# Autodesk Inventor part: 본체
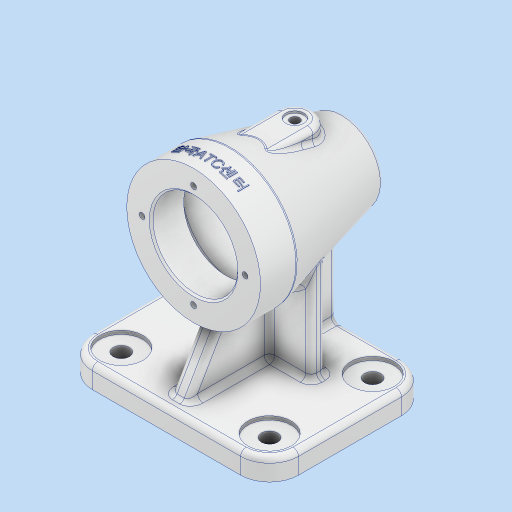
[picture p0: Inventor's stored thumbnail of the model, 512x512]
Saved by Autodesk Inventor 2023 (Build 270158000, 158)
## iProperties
Created: 2024-12
Part Number: 본체
Material: 알루미늄 6061
Document SubType Name: Modeling
Designer: asung
Density: 2.7 g/cm^3
Appearance: 알루미늄 - 평지
Mass: 739.493 g
Surface Area: 674.499 cm^2
Volume: 273.886 cm^3
Author: asung
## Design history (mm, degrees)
sketch "스케치1"
  geometry: L1 (-5744.5, -45.233)-(-5744.5, 45.233); L2 (5744.5, 45.233)-(5744.5, -45.233); L3 (41, -44.5)-(-41, -44.5); L4 (-57, -28.5)-(-57, 28.5); L5 (-41, 44.5)-(41, 44.5); L6 (57, 28.5)-(57, -28.5); L7 (57, -44.5)-(-57, 44.5); L8 (-57, -44.5)-(57, 44.5); A1 r 16 centre (41, -28.5) between (41, -44.5) and (57, -28.5); A2 r 16 centre (-41, -28.5) between (-57, -28.5) and (-41, -44.5); A3 r 16 centre (-41, 28.5) between (-41, 44.5) and (-57, 28.5); A4 r 16 centre (41, 28.5) between (57, 28.5) and (41, 44.5); 1 further point
  constraints: 16 end point, 8 point on circle, 8 point on line, 8 tangent, 4 centre point, 3 equal radius, 3 parallel, 2 midpoint, 1 horizontal, 1 perpendicular
  dimensions: "d1" = 114 distance of L7.end L8.end; "d2" = 89 distance of L8.start L7.end; "d3" = 16 radius of A1
extrude "돌출1" new body sketch "스케치1" distance "d4" = 12; taper "d5" = 0 deg
sketch "스케치2"
  geometry: A1 r 16 centre (41, -28.5) between (41, -44.5) and (57, -28.5) reference; A2 r 16 centre (41, 28.5) between (57, 28.5) and (41, 44.5) reference; A3 r 16 centre (-41, 28.5) between (-41, 44.5) and (-57, 28.5) reference; A4 r 16 centre (-41, -28.5) between (-57, -28.5) and (-41, -44.5) reference; 1 further point
hole "구멍1" sketch "스케치2" at (-41, 28.5), (-41, -28.5), (41, -28.5), (41, 28.5) diameter "d6" = 9; stored, may be unused: countersink angle "d10" = 90 deg, drill point angle "d12" = 0 deg; dims "d7" = 6, "d8" = 24, "d9" = 2, "d11" = 12
node "작업 평면1"
sketch "스케치4"
  geometry: L1 (73, 12)-(73, 0) reference; L2 (73, 0)-(-16, 0) reference; L3 (-16, 0)-(-16, 12) reference; L4 (-16, 12)-(73, 12) reference; L5 (73, 0)-(57, 0) reference; L6 (58, 82)-(58, 0); L7 (58, 82)-(-26, 82); L8 (-26, 82)-(-26, 103); L9 (58, 82)-(58, 119); L10 (58, 119)-(38, 119); L11 (38, 119)-(-26, 103); 1 further point
  constraints: 12 end point, 3 vertical, 2 horizontal
  dimensions: "d23" = 82 distance of L6.start L6.end; "d24" = 15 distance of L1.end L6.end; "d25" = 0 vertical distance of L1.end L6.end; "d26" = 84 distance of L6.start L7.end; "d29" = 37 distance of L6.start L9.end; "d30" = 20 distance of L9.end L10.end; "d118" = 42 diameter of L8.end L7
revolve "회전1" sketch "스케치4" stored, may be unused: angle "d32" = 90 deg
node "작업 평면2"
sketch "스케치5"
  geometry: L1 (-16.733, 29.5)-(16.733, 29.5) reference; L2 (16.733, 29.5)-(16.733, 9.5) reference; L3 (-16.733, 9.5)-(-16.733, 29.5) reference; L4 (-21, -54.5)-(21, -54.5) reference; L5 (-37, 9.5)-(37, 9.5) reference; L6 (-37, 9.5)-(37, 9.5) reference; L7 (-37, 29.5)-(37, 29.5) reference; L8 (-37, 29.5)-(37, 29.5) reference; L9 (0, 29.5)-(0, -26.5); L10 (10, -26.5)-(10, 4.324); L11 (-10, -26.5)-(-10, 7.832); L12 (-10, 7.832)-(10, 7.832); L13 (10, 7.832)-(10, 4.324); A1 r 10 centre (0, -26.5) between (10, -26.5) and (-10, -26.5); 3 further points
  constraints: 10 end point, 2 perpendicular, 2 point on circle, 2 tangent, 2 vertical, 1 centre point, 1 coincident, 1 midpoint, 1 parallel, 1 point on line, 1 other
  dimensions: "d35" = 56 distance of L9.start L9.end; "d36" = 20 diameter of A1
extrude "돌출2" join sketch "스케치5" stored distance "d37" = 12; taper "d38" = 0 deg
sketch "스케치6"
  geometry: L1 (58, 119)-(58, 45) reference; L2 (58, 45)-(38, 45) reference; L3 (38, 45)-(-26, 61) reference; L4 (-26, 61)-(-26, 103) reference; L5 (-26, 103)-(-8, 107.5) reference; L6 (-8, 107.5)-(-8, 115) reference; L7 (-8, 115)-(22, 115) reference; L8 (22, 115)-(38, 119) reference; L9 (38, 119)-(58, 119) reference; L10 (-16, 0)-(-16, 12) reference; L11 (-16, 12)-(73, 12) reference; L12 (73, 12)-(73, 0) reference; L13 (73, 0)-(-16, 0) reference; L14 (-16, 0)-(-16, 12) reference; L15 (-16, 12)-(-16, 65.487); L16 (35.119, 65.487)-(66, 12); L17 (58, 119)-(58, 45) reference; L18 (-26, 61)-(-26, 103) reference; L19 (-26, 103)-(-8, 107.5) reference; L20 (-8, 107.5)-(-8, 115) reference; L21 (-8, 115)-(22, 115) reference; L22 (38, 119)-(58, 119) reference; L23 (-16, 0)-(-16, 12) reference; L24 (-16, 12)-(73, 12) reference; L25 (73, 12)-(73, 0) reference; L26 (73, 0)-(-16, 0) reference; L27 (-16, 65.487)-(35.119, 65.487); L28 (22, 115)-(38, 119) reference; 2 further points; 2 other entities
  constraints: 6 end point, 1 horizontal, 1 point on line, 1 vertical, 2 other
  dimensions: "d39" = 7 distance from line of L12 L16.end; "d40" = 60 deg angle of L11 L16; "d41" = 65.48678 distance between parallel lines of L13 L27
extrude "돌출3" join sketch "스케치6" stored distance "d42" = 10; taper "d43" = 0 deg
node "작업 평면3"
sketch "스케치7"
  geometry: L1 (51, 115)-(51, 111.079) reference; L2 (46, 51.659)-(46, 12) reference; L3 (46, 12)-(98, 12) reference; L4 (98, 12)-(98, 0) reference; L5 (98, 0)-(-16, 0) reference; L6 (-16, 0)-(-16, 12) reference; L7 (-16, 12)-(36, 12) reference; L8 (36, 12)-(36, 51.659) reference; L9 (31, 111.079)-(31, 115) reference; L10 (31, 115)-(51, 115) reference; L11 (69, 69.289)-(69, 12); L12 (13, 69.289)-(13, 12); A1 r 30.75 centre (41, 82) between (46, 51.659) and (51, 111.079) reference; A2 r 30.75 centre (41, 82) between (31, 111.079) and (36, 51.659) reference; 1 further point
  constraints: 4 end point, 2 point on circle, 2 point on line, 2 vertical
  dimensions: "d45" = 56 distance of L12.end L11.end; "d46" = 28 horizontal distance of point (41, 0) L11.end
  node "절단 모서리 투영5"
feature "리브1" dims "d47" = 1, "d48" = 8, "d49" = 0, "d50" = 0, "d51" = 1, "d52" = 1
feature "리브2" dims "d53" = 1, "d54" = 8, "d55" = 0, "d56" = 0, "d57" = 1, "d58" = 1
sketch "스케치8"
  geometry: C1 r 37 at (0, 0) reference; 2 further points
  constraints: 1 coincident
hole "구멍2" sketch "스케치8" at (0, 0) diameter "d59" = 47; stored, may be unused: countersink angle "d63" = 90 deg, drill point angle "d65" = 0 deg; dims "d60" = 6, "d61" = 24, "d62" = 2, "d64" = 18
chamfer "모따기1" distance "d66" = 1; stored, may be unused: second distance "d67" = 2, angle "d68" = 45 deg
sketch "스케치9"
  geometry: L1 (61, -54.5)-(58.5, -44.5) reference; L2 (58.5, -44.5)-(0, -44.5) reference; L3 (0, -44.5)-(0, 44.5) reference; L4 (0, 44.5)-(12, 44.5) reference; L5 (12, 44.5)-(12, 37.5) reference; L6 (12, 37.5)-(45, 18.447) reference; L7 (45, 18.447)-(45, 29.5) reference; L8 (45, 29.5)-(57.5, 29.5) reference; L9 (57.5, 29.5)-(58.5, 28.5) reference; L10 (58.5, 28.5)-(58.5, 11.5) reference; L11 (58.5, 11.5)-(105.5, 11.5) reference; L12 (105.5, 11.5)-(105.5, 28.5) reference; L13 (105.5, 28.5)-(106.5, 29.5) reference; L14 (106.5, 29.5)-(119, 29.5) reference; L15 (119, 29.5)-(119, 9.5) reference; L16 (119, 9.5)-(115, -6.5) reference; L17 (115, -6.5)-(115, -36.5) reference; L18 (115, -36.5)-(107.5, -36.5) reference; L19 (107.5, -36.5)-(103, -54.5) reference; L20 (103, -54.5)-(61, -54.5) reference; L21 (112.793, 5.287)-(103.664, -31.228); L22 (82, -33.5)-(100.754, -33.5); L23 (105.5, 11.5)-(58.5, 11.5) reference; L24 (82, 11.5)-(82, -33.5); L25 (82, 11.5)-(107.942, 11.5); A1 r 5 centre (107.942, 6.5) between (112.793, 5.287) and (107.942, 11.5); A2 r 3 centre (100.754, -30.5) between (100.754, -33.5) and (103.664, -31.228); 3 further points
  constraints: 9 end point, 5 tangent, 4 point on circle, 3 parallel, 2 centre point, 1 midpoint
  dimensions: "d69" = 5 distance between parallel lines of L16 L21; "d70" = 45 distance between parallel lines of L11 L22; "d71" = 5 radius of A1; "d72" = 3 radius of A2
revolve "회전2" sketch "스케치9" stored, may be unused: angle "d73" = 90 deg
sketch "스케치10"
  geometry: C1 r 18.754 at (0, 0) reference; 2 further points
  constraints: 1 coincident
hole "구멍3" sketch "스케치10" at (0, 0) diameter "d74" = 31; stored, may be unused: countersink angle "d78" = 90 deg, drill point angle "d80" = 0 deg; dims "d75" = 6, "d76" = 35, "d77" = 10, "d79" = 13
fillet "모깎기1" dims "d81" = 0.3
sketch "스케치11" dims "d82" = 57
  geometry: C1 r 37 at (0, 0) reference; C2 r 24.5 at (0, 0) reference; 3 further points
  constraints: 2 vertical alignment, 1 coincident, 2 other
hole "구멍4" sketch "스케치11" at (0, 28.5) diameter "d83" = 3.242; stored, may be unused: countersink angle "d87" = 90 deg, drill point angle "d89" = 118 deg; dims "d84" = 8, "d85" = 35, "d86" = 10, "d88" = 10
sketch "스케치12"
  geometry: C1 r 5 at (0, 26.5); A1 r 10 centre (0, 26.5) between (10, 26.5) and (-10, 26.5) reference; 1 further point
  constraints: 1 centre point, 1 coincident
  dimensions: "d93" = 10 diameter of C1
extrude "돌출4" cut sketch "스케치12" distance "d94" = 1; taper "d95" = 0 deg
sketch "스케치13"
  geometry: C1 r 5 at (0, 0) reference; 2 further points
  constraints: 1 coincident
hole "구멍5" sketch "스케치13" at (0, 0) diameter "d96" = 5.1881; stored, may be unused: countersink angle "d100" = 90 deg, drill point angle "d102" = 118 deg; dims "d97" = 20, "d98" = 4, "d99" = 2, "d101" = 25
node "작업 평면4"
sketch "스케치14"
  geometry: L1 (-37, 10)-(37, 10) reference; L2 (5, -10)-(5, -1.249) reference; L3 (-5, -1.249)-(-5, -10) reference; L4 (5, -10)-(-5, -10) reference; 4 further points; 1 other entity
  constraints: 1 midpoint, 1 vertical alignment, 2 other
  dimensions: "d103" = 9 distance of point (0, 10) point (0, 1)
feature "엠보싱1" sketch "스케치14" dims "d104" = 0.5, "d105" = 0
fillet "모깎기4" dims "d108" = 3
fillet "모깎기5" dims "d109" = 3
fillet "모깎기6" dims "d110" = 3
fillet "모깎기9" dims "d113" = 3
fillet "모깎기10" dims "d114" = 3
fillet "모깎기11" dims "d115" = 3
fillet "모깎기12" dims "d116" = 3
fillet "모깎기13" dims "d117" = 3
node "작업 평면5"
sketch "스케치15"
  geometry: L1 (23.5, 28.5)-(24.5, 29.5) reference; L2 (24.5, 29.5)-(26.879, 29.5) reference; L3 (26.879, 29.5)-(26.879, 19.5) reference; L4 (26.879, 19.5)-(28.5, 18.526) reference; L5 (28.5, 18.526)-(30.121, 19.5) reference; L6 (30.121, 19.5)-(30.121, 29.5) reference; L7 (30.121, 29.5)-(37, 29.5) reference; L8 (37, 29.5)-(37, 9.869) reference; L9 (36.91, 9.142)-(21, -54.5) reference; L10 (-21, -54.5)-(-36.91, 9.142) reference; L11 (-37, 9.869)-(-37, 29.5) reference; L12 (-37, 29.5)-(-30.121, 29.5) reference; L13 (-30.121, 29.5)-(-30.121, 19.5) reference; L14 (-30.121, 19.5)-(-28.5, 18.526) reference; L15 (-28.5, 18.526)-(-26.879, 19.5) reference; L16 (-26.879, 19.5)-(-26.879, 29.5) reference; L17 (-26.879, 29.5)-(-24.5, 29.5) reference; L18 (-24.5, 29.5)-(-23.5, 28.5) reference; L19 (-23.5, 28.5)-(-23.5, 11.5) reference; L20 (-23.5, 11.5)-(-25.942, 11.5) reference; L21 (-30.793, 5.287)-(-21.664, -31.228) reference; L22 (-18.754, -33.5)-(-17.5, -33.5) reference; L23 (-17.5, -33.5)-(-17.5, -43.2) reference; L24 (-17.2, -43.5)-(-15.5, -43.5) reference; L25 (-12.5, -46.5)-(12.5, -46.5) reference; L26 (15.5, -43.5)-(17.2, -43.5) reference; L27 (17.5, -43.2)-(17.5, -33.5) reference; L28 (17.5, -33.5)-(18.754, -33.5) reference; L29 (21.664, -31.228)-(30.793, 5.287) reference; L30 (25.942, 11.5)-(23.5, 11.5) reference; L31 (23.5, 11.5)-(23.5, 28.5) reference; L32 (21, -54.5)-(-21, -54.5) reference; A1 r 3 centre (34, 9.869) between (36.91, 9.142) and (37, 9.869) reference; A2 r 3 centre (-34, 9.869) between (-37, 9.869) and (-36.91, 9.142) reference; A3 r 5 centre (-25.942, 6.5) between (-25.942, 11.5) and (-30.793, 5.287) reference; A4 r 3 centre (-18.754, -30.5) between (-21.664, -31.228) and (-18.754, -33.5) reference; A5 r 0.3 centre (-17.2, -43.2) between (-17.5, -43.2) and (-17.2, -43.5) reference; A6 r 3 centre (-12.5, -43.5) between (-15.5, -43.5) and (-12.5, -46.5) reference; A7 r 3 centre (12.5, -43.5) between (12.5, -46.5) and (15.5, -43.5) reference; A8 r 0.3 centre (17.2, -43.2) between (17.2, -43.5) and (17.5, -43.2) reference; A9 r 3 centre (18.754, -30.5) between (18.754, -33.5) and (21.664, -31.228) reference; A10 r 5 centre (25.942, 6.5) between (30.793, 5.287) and (25.942, 11.5) reference; 1 further point
  node "절단 모서리 투영7"
sketch "스케치16"
  geometry: L1 (23.5, 28.5)-(24.5, 29.5) reference; L2 (24.5, 29.5)-(26.879, 29.5) reference; L3 (26.879, 29.5)-(26.879, 19.5) reference; L4 (26.879, 19.5)-(28.5, 18.526) reference; L5 (28.5, 18.526)-(30.121, 19.5) reference; L6 (30.121, 19.5)-(30.121, 29.5) reference; L7 (30.121, 29.5)-(37, 29.5) reference; L8 (37, 29.5)-(37, 9.869) reference; L9 (36.91, 9.142)-(21, -54.5) reference; L10 (21, -54.5)-(-21, -54.5) reference; L11 (-21, -54.5)-(-36.91, 9.142) reference; L12 (-37, 9.869)-(-37, 29.5) reference; L13 (-37, 29.5)-(-30.121, 29.5) reference; L14 (-30.121, 29.5)-(-30.121, 19.5) reference; L15 (-30.121, 19.5)-(-28.5, 18.526) reference; L16 (-28.5, 18.526)-(-26.879, 19.5) reference; L17 (-26.879, 19.5)-(-26.879, 29.5) reference; L18 (-26.879, 29.5)-(-24.5, 29.5) reference; L19 (-24.5, 29.5)-(-23.5, 28.5) reference; L20 (-23.5, 28.5)-(-23.5, 11.5) reference; L21 (-23.5, 11.5)-(-25.942, 11.5) reference; L22 (-30.793, 5.287)-(-21.664, -31.228) reference; L23 (-18.754, -33.5)-(-17.5, -33.5) reference; L24 (-17.5, -33.5)-(-17.5, -43.2) reference; L25 (-17.2, -43.5)-(-15.5, -43.5) reference; L26 (-12.5, -46.5)-(12.5, -46.5) reference; L27 (15.5, -43.5)-(17.2, -43.5) reference; L28 (17.5, -43.2)-(17.5, -33.5) reference; L29 (17.5, -33.5)-(18.754, -33.5) reference; L30 (21.664, -31.228)-(30.793, 5.287) reference; L31 (25.942, 11.5)-(23.5, 11.5) reference; L32 (23.5, 11.5)-(23.5, 28.5) reference; A1 r 3 centre (34, 9.869) between (36.91, 9.142) and (37, 9.869) reference; A2 r 3 centre (-34, 9.869) between (-37, 9.869) and (-36.91, 9.142) reference; A3 r 5 centre (-25.942, 6.5) between (-25.942, 11.5) and (-30.793, 5.287) reference; A4 r 3 centre (-18.754, -30.5) between (-21.664, -31.228) and (-18.754, -33.5) reference; A5 r 0.3 centre (-17.2, -43.2) between (-17.5, -43.2) and (-17.2, -43.5) reference; A6 r 3 centre (-12.5, -43.5) between (-15.5, -43.5) and (-12.5, -46.5) reference; A7 r 3 centre (12.5, -43.5) between (12.5, -46.5) and (15.5, -43.5) reference; A8 r 0.3 centre (17.2, -43.2) between (17.2, -43.5) and (17.5, -43.2) reference; A9 r 3 centre (18.754, -30.5) between (18.754, -33.5) and (21.664, -31.228) reference; A10 r 5 centre (25.942, 6.5) between (30.793, 5.287) and (25.942, 11.5) reference; 1 further point
  dimensions: "d120" = 42 distance of L10.end L9.end (derived)
  node "절단 모서리 투영8"
fillet "모깎기14" dims "d121" = 3
feature "Ӿ耀Ԁ耀Ԃ耀Ԅ耀Ԇ耀Ԉ耀Ԋ耀Ԍ耀" dims "d1" = 114, "d2" = 89, "d3" = 16, "d4" = 12, "d5" = 0, "d6" = 9, "d7" = 6, "d8" = 24, "d9" = 2, "d10" = 90 deg, "d11" = 12, "d12" = 0, "d23" = 82, "d24" = 15, "d25" = 0, "d26" = 84, "d29" = 37, "d30" = 20, "d32" = 90 deg, "d33" = -115, "d35" = 56, "d36" = 20, "d37" = 12, "d38" = 0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
node "솔리드1"
pattern_circular "원형 패턴1" dims angle "d91" = 360 deg
node "투영된 루프1"
node "투영된 루프2"
node "투영된 루프3"
node "절단 모서리 투영1"
node "절단 모서리 투영2"
node "절단 모서리 투영3"
node "절단 모서리 투영4"
node "절단 모서리 투영6"
feature "A9D066F2-1C7D-4E18-AEED-F7BC21143FA4" dims "d6" = 9, "d7" = 6, "d8" = 24, "d9" = 2, "d10" = 90 deg, "d11" = 12, "d12" = 0
